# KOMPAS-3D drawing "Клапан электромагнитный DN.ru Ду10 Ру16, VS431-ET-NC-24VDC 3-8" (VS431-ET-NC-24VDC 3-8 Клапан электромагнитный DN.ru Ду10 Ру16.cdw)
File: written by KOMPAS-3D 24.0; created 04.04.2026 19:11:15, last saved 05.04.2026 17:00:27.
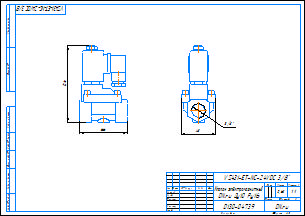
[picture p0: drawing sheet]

Document properties: c3d_UniqueCompID: ef56311e-7521-43dc-8291-0e6108b3d81d; Обозначение: VS400-ET-NC-220VAC 3-8; Наименование: Клапан электромагнитный DN.ru Ду10 Ру16; Автор: artio; Класс точности: c; Знак неуказанной шероховатости: Шероховатость не задана; Рассекать на разрезах: Да; Автор: artio; Форматы листов документа: A3; Полное имя файла: ..\VS400-ET-NC-24VDC 3-8 Клапан электромагнитный DN.ru Ду10 Ру16.cdw; Масса: 0.62; Наименование: Клапан электромагнитный DN.ru Ду10 Ру16; Количество листов документа: 1; Примечание: D130-04739

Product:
- Body: Тело 1  | qty 1
    Масса: 1.030062
- Part/product: Клапан электромагнитный DN.ru Ду10 Ру16  | designation VS431-ET-NC-24VDC 3-8
    Масса: 0.62
    Раздел спецификации: Прочие изделия
    Форматы листов документа: A3
    Примечание: D130-04739
    additional columns: ef56311e-7521-43dc-8291-0e6108b3d81d; VS400-ET-NC-220VAC 3-8; artio; c; Шероховатость не задана; Да

Views: Вид 1, Спереди, Проекционный вид 2
Referenced files in C:\Users\artio\OneDrive\Рабочий стол\Клапан электромагнитный DN.ru\VS400-ET-NC\VS400-ET-NC-24VDC\: VS400-ET-NC-24VDC 3-8 Клапан электромагнитный DN.ru Ду10 Ру16.m3d
Referenced files in C:\Users\artio\OneDrive\Рабочий стол\Клапан электромагнитный DN.ru\VS431\VS431-ET-NC\VS431-ET-NC-24VDC\Ду10\: VS431-ET-NC-24VDC 3-8 Клапан электромагнитный DN.ru Ду10 Ру16.m3d, VS431-ET-NC-24VDC 3-8 Клапан электромагнитный DN.ru Ду10 Ру16.cdw
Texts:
  VS431-ET-NC-24VDC 3-8
  Клапан электромагнитный
  DN.ru Ду10 Ру16
  VS431-ET-NC-24VDC 3/8"
  VS431-ET-NC-24VDC 3/8"-
  Клапан электромагнитный DN.ru Ду10 Ру16
  VS431-ET-NC-24VDC 3-8 Клапан электромагнитный DN.ru Ду10 Ру16
Dimensions and other numbers on the sheet: 0; 3; 2; 4; 48; 3/8"; 66; 106; 1:1; 1; 0,62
